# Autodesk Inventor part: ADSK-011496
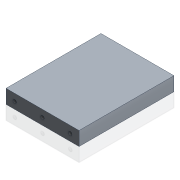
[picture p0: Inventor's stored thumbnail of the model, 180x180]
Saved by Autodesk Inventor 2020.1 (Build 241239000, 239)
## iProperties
Created: 2000-02
Part Number: ADSK-011496
Material: Pearson Aluminium
Description: PLT-06,FA,CP,07,040,051,CCCCCC,MANDREL,COMP
Document SubType Name: Modeling
Designer: sspink
Density: 2.71 g/cm^3
Appearance: Pearson-Aluminum
Mass: 666.181 g
Surface Area: 358.599 cm^2
Volume: 245.823 cm^3
Control State: 0
Checked Out: False
Master: False
Shininess: 35.0
Length Units: 11269
Angle Units: 11279
Time Units: 11290
Mass Units: 11283
Length Display Precision: 3
Angle Display Precision: 2
Compacted: True
Cutlength: 5.13
Material Desc: FLAT,ALUM,0.75 X 4.00
Material_number: A084928
Dimensions: 100x19x130 mm
Mass: 0,666 kg
Density: 2.71
Volumn: 249.6679542535019
Area: 370.8931327509912
PropertySet Name: Model Information
Author: sspink
Revision Number: -
Title: PLT-06,FA,CP,07,040,051,CCCCCC,MANDREL,COMP
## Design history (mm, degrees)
sketch "Sketch3"
  geometry: 3 further points
node "Hole2" dims "d14" = 4.134, "d15" = 9.525, "d16" = 6.35, "d17" = 60 deg, "d18" = 14.2, "d19" = 118 deg, "d22" = 10
node "Solide1"
  node "Extrusion1" dims "d2" = 130, "d3" = 0
  node "Hole1" dims "d6" = 4.134, "d7" = 9.525, "d8" = 6.35, "d9" = 60 deg, "d10" = 14.2, "d11" = 118 deg, "d21" = 10
sketch "Sketch1"
  geometry: L1 (-50, -9.5)-(50, -9.5); L2 (50, -9.5)-(50, 9.5); L3 (50, 9.5)-(-50, 9.5); L4 (-50, 9.5)-(-50, -9.5); 3 further points
  constraints: 8 end point, 2 midpoint, 2 parallel, 1 horizontal, 1 horizontal alignment, 1 perpendicular, 1 vertical alignment
  dimensions: "d0" = 19 distance between parallel lines of L1 L3; "d1" = 100 distance between parallel lines of L2 L4
sketch "Sketch2"
  geometry: L1 (50, -9.5)-(-50, -9.5) reference; L2 (-50, -9.5)-(-50, 9.5) reference; L3 (-38, 0)-(38, 0); 4 further points
  constraints: 3 midpoint, 2 end point, 1 coincident, 1 horizontal, 1 horizontal alignment, 1 vertical alignment
  dimensions: "d20" = 76 distance of L3.start L3.end
node "Corps solides"
node "Corps surfaciques"
